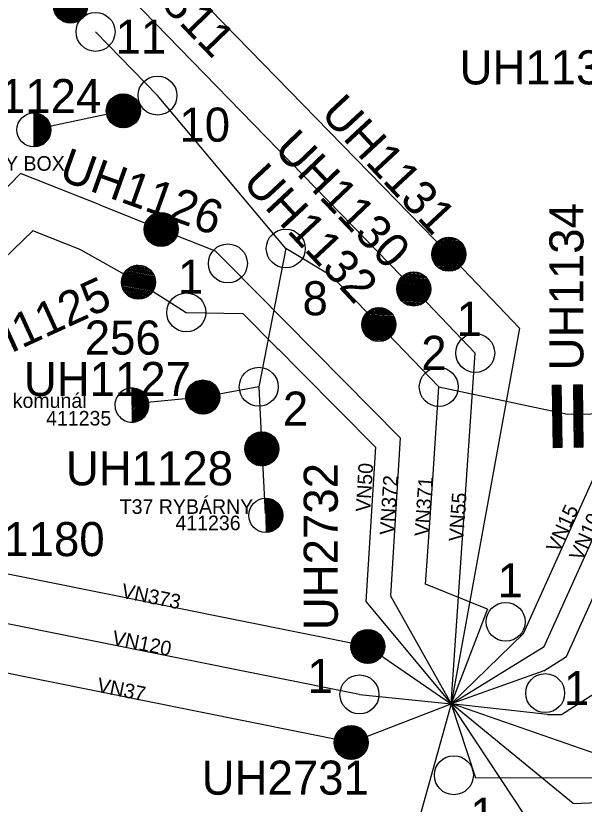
# Model space of a CAD drawing. Extents: x -541380 to -536551, y -1184364 to -1179471.
# Drawn here: x -537971 to -537387, y -1180734 to -1179924 of the extents above; entities that cross this region are included whole.
import ezdxf

# ---------------------------------------------------------------- set-up
doc = ezdxf.new("R2010")
doc.units = 0
for name, color, linetype in [('Default', 7, 'Continuous'), ('Vrstva 1', 7, 'Continuous'), ('Vrstva 2', 7, 'Continuous'), ('Vrstva 3', 7, 'Continuous'), ('Vrstva 5', 7, 'Continuous')]:
    doc.layers.add(name, color=color, linetype=linetype)

# ---------------------------------------------------------------- blocks, each defined once
blk = doc.blocks.new('PS100')
at = {"layer": 'Default'}
for p, q in [((-17.47, -0.71), (0.71, 17.47)), ((-17.47, 0.7), (-0.7, 17.47)), ((-17.37, -2.02), (2.02, 17.37)), ((-17.34, 2.25), (-2.25, 17.34)), ((-17.18, -3.25), (3.25, 17.18)), ((-17.03, 3.97), (-3.97, 17.03)), ((-16.92, -4.41), (4.41, 16.92)), ((-16.6, -5.5), (5.5, 16.6)), ((-16.43, 5.99), (-5.99, 16.43)), ((-16.22, -6.53), (6.53, 16.22)), ((-15.79, -7.52), (7.52, 15.79)), ((-15.31, -8.45), (8.45, 15.31)), ((-15.22, 8.61), (-8.61, 15.22)), ((-14.78, -9.34), (9.34, 14.78)), ((-14.22, -10.18), (10.18, 14.22)), ((-13.6, -10.99), (10.99, 13.6)), ((-12.95, -11.75), (11.75, 12.95)), ((-12.26, -12.47), (12.47, 12.26)), ((-11.53, -13.15), (13.15, 11.53)), ((-10.75, -13.79), (13.79, 10.75)), ((-9.94, -14.39), (14.39, 9.94)), ((-9.08, -14.95), (14.95, 9.08)), ((-8.18, -15.46), (15.46, 8.18)), ((-7.23, -15.92), (15.92, 7.23)), ((-6.23, -16.34), (16.34, 6.23)), ((-5.18, -16.7), (16.7, 5.18)), ((-4.07, -17.01), (17.01, 4.07)), ((-2.89, -17.25), (17.25, 2.89)), ((-1.64, -17.41), (17.41, 1.64)), ((-0.3, -17.48), (17.48, 0.3)), ((1.15, -17.45), (17.45, -1.15)), ((2.74, -17.27), (17.27, -2.74)), ((4.54, -16.89), (16.89, -4.54)), ((6.68, -16.16), (16.16, -6.68)), ((9.71, -14.54), (14.54, -9.71))]:
    blk.add_line(p, q, dxfattribs=at)
blk.add_circle((0, 0), 17.49, dxfattribs=at)
blk = doc.blocks.new('PS140')
at = {"layer": 'Default'}
for p, q in [((-17.49, -0.01), (0.01, 17.49)), ((-17.43, -1.37), (1.37, 17.43)), ((-17.42, 1.47), (-1.47, 17.42)), ((-17.29, -2.63), (2.63, 17.29)), ((-17.21, 3.1), (-3.1, 17.21)), ((-17.06, -3.82), (3.82, 17.06)), ((-16.77, -4.95), (4.95, 16.77)), ((-16.77, 4.95), (-4.95, 16.77)), ((-16.42, -6.01), (6.01, 16.42)), ((-16.02, -7.02), (7.02, 16.02)), ((-15.93, 7.2), (-7.2, 15.93)), ((-15.56, -7.98), (7.98, 15.56)), ((-15.06, -8.89), (8.89, 15.06)), ((-14.51, -9.76), (9.76, 14.51)), ((-13.92, -10.58), (10.58, 13.92)), ((-13.75, 10.8), (-10.8, 13.75)), ((-13.29, -11.36), (11.36, 13.29)), ((-12.62, -12.11), (12.11, 12.62)), ((-11.91, -12.81), (12.81, 11.91)), ((-11.15, -13.47), (13.47, 11.15)), ((-10.36, -14.09), (14.09, 10.36)), ((-9.52, -14.67), (14.67, 9.52)), ((-8.64, -15.2), (15.2, 8.64)), ((-7.72, -15.69), (15.69, 7.72)), ((-6.74, -16.13), (16.13, 6.74)), ((-5.72, -16.52), (16.52, 5.72)), ((-4.64, -16.86), (16.86, 4.64)), ((-3.5, -17.13), (17.13, 3.5)), ((-2.29, -17.34), (17.34, 2.29)), ((-1, -17.46), (17.46, 1)), ((0.39, -17.48), (17.48, -0.39)), ((1.91, -17.38), (17.38, -1.91)), ((3.59, -17.11), (17.11, -3.59)), ((5.53, -16.59), (16.59, -5.53)), ((7.96, -15.57), (15.57, -7.96))]:
    blk.add_line(p, q, dxfattribs=at)
blk.add_circle((0, 0), 17.49, dxfattribs=at)
blk = doc.blocks.new('PS150')
at = {"layer": 'Default'}
for p, q in [((-15.07, 22.36), (-7.37, 30.07)), ((-15.07, 23.78), (-8.78, 30.07)), ((-15.07, 25.19), (-10.2, 30.07)), ((-15.07, 26.6), (-11.61, 30.07)), ((-15.07, 28.02), (-13.03, 30.07)), ((-15.07, 29.43), (-14.44, 30.07)), ((-15.07, 20.95), (-6.51, 29.51)), ((-15.07, 19.53), (-6.51, 28.1)), ((-15.07, 18.12), (-6.51, 26.69)), ((-15.07, 16.71), (-6.51, 25.27)), ((6.66, 22.61), (14.12, 30.07)), ((6.66, 24.02), (12.7, 30.06)), ((6.66, 25.43), (11.29, 30.06)), ((6.66, 26.85), (9.87, 30.06)), ((6.66, 28.26), (8.46, 30.06)), ((6.66, 29.68), (7.04, 30.06)), ((6.66, 21.19), (15.22, 29.76)), ((6.66, 19.78), (15.22, 28.34)), ((6.66, 18.36), (15.22, 26.93)), ((6.66, 16.95), (15.22, 25.51)), ((-15.07, 15.29), (-6.51, 23.86)), ((-15.07, 13.88), (-6.51, 22.44)), ((-15.07, 12.46), (-6.51, 21.03)), ((-15.07, 11.05), (-6.51, 19.61)), ((-15.07, 9.64), (-6.51, 18.2)), ((-15.07, 8.22), (-6.51, 16.79)), ((6.66, 15.54), (15.22, 24.1)), ((6.66, 14.12), (15.22, 22.69)), ((6.66, 12.71), (15.22, 21.27)), ((6.66, 11.29), (15.22, 19.86)), ((6.66, 9.88), (15.22, 18.44)), ((6.66, 8.46), (15.22, 17.03)), ((-15.07, 6.81), (-6.51, 15.37)), ((-15.07, 5.39), (-6.51, 13.96)), ((-15.07, 3.98), (-6.5, 12.54)), ((-15.07, 2.56), (-6.5, 11.13)), ((-15.07, 1.15), (-6.5, 9.72)), ((-15.07, -0.26), (-6.5, 8.3)), ((6.66, 7.05), (15.22, 15.62)), ((6.66, 5.64), (15.22, 14.2)), ((6.66, 4.22), (15.22, 12.79)), ((6.66, 2.81), (15.22, 11.37)), ((6.66, 1.39), (15.22, 9.96)), ((6.66, -0.02), (15.22, 8.55)), ((-15.07, -1.68), (-6.5, 6.89)), ((-15.07, -3.09), (-6.5, 5.47)), ((-15.07, -4.51), (-6.5, 4.06)), ((-15.07, -5.92), (-6.5, 2.65)), ((-15.07, -7.33), (-6.5, 1.23)), ((6.66, -1.43), (15.22, 7.13)), ((6.66, -2.85), (15.22, 5.72)), ((6.66, -4.26), (15.22, 4.3)), ((6.66, -5.68), (15.22, 2.89)), ((6.66, -7.09), (15.22, 1.47)), ((6.66, -8.5), (15.22, 0.06)), ((-15.07, -8.75), (-6.5, -0.18)), ((-15.07, -10.16), (-6.5, -1.6)), ((-15.07, -11.58), (-6.5, -3.01)), ((-15.07, -12.99), (-6.5, -4.43)), ((-15.07, -14.4), (-6.5, -5.84)), ((-15.07, -15.82), (-6.5, -7.25)), ((6.66, -9.92), (15.22, -1.35)), ((6.66, -11.33), (15.22, -2.77)), ((6.66, -12.75), (15.22, -4.18)), ((6.66, -14.16), (15.23, -5.6)), ((6.66, -15.58), (15.23, -7.01)), ((-15.07, -17.23), (-6.5, -8.67)), ((-15.07, -18.65), (-6.5, -10.08)), ((-15.07, -20.06), (-6.5, -11.5)), ((-15.07, -21.48), (-6.5, -12.91)), ((-15.07, -22.89), (-6.5, -14.32)), ((-15.07, -24.3), (-6.5, -15.74)), ((6.66, -16.99), (15.23, -8.42)), ((6.66, -18.4), (15.23, -9.84)), ((6.66, -19.82), (15.23, -11.25)), ((6.66, -21.23), (15.23, -12.67)), ((6.66, -22.65), (15.23, -14.08)), ((6.66, -24.06), (15.23, -15.49)), ((-15.07, -25.72), (-6.5, -17.15)), ((-15.07, -27.13), (-6.5, -18.57)), ((-15.07, -28.55), (-6.5, -19.98)), ((-15.07, -29.96), (-6.5, -21.39)), ((-15.07, -31.37), (-6.5, -22.81)), ((-15.07, -32.79), (-6.5, -24.22)), ((6.66, -25.47), (15.23, -16.91)), ((6.66, -26.89), (15.23, -18.32)), ((6.66, -28.3), (15.23, -19.74)), ((6.66, -29.72), (15.23, -21.15)), ((6.66, -31.13), (15.23, -22.57)), ((6.66, -32.54), (15.23, -23.98)), ((-15.02, -34.16), (-6.5, -25.64)), ((-13.61, -34.16), (-6.5, -27.05)), ((-12.2, -34.16), (-6.5, -28.47)), ((-10.78, -34.16), (-6.5, -29.88)), ((-9.37, -34.16), (-6.5, -31.29)), ((6.66, -33.96), (15.23, -25.39)), ((7.87, -34.16), (15.23, -26.81)), ((9.29, -34.16), (15.23, -28.22)), ((10.7, -34.16), (15.23, -29.64)), ((12.12, -34.16), (15.23, -31.05)), ((-7.95, -34.16), (-6.5, -32.71)), ((-6.54, -34.16), (-6.5, -34.12)), ((13.53, -34.16), (15.23, -32.46)), ((14.95, -34.16), (15.23, -33.88))]:
    blk.add_line(p, q, dxfattribs=at)
for points in [[(-6.51, 30.07), (-6.5, -34.16), (-15.07, -34.16), (-15.07, 30.07)], [(15.22, 30.07), (15.23, -34.16), (6.66, -34.16), (6.66, 30.06)]]:
    blk.add_lwpolyline(points, close=True, dxfattribs=at)
blk = doc.blocks.new('PS610')
at = {"layer": 'Default'}
for p, q in [((0, 16.16), (1.27, 17.43)), ((0, 14.75), (2.54, 17.29)), ((0, 13.33), (3.75, 17.09)), ((0, 11.92), (4.86, 16.79)), ((0, 10.51), (5.93, 16.44)), ((0, 9.09), (6.95, 16.05)), ((0, 7.68), (7.9, 15.58)), ((0, 6.26), (8.83, 15.1)), ((0, 4.85), (9.69, 14.54)), ((0, 3.44), (10.52, 13.96)), ((0, 2.02), (11.3, 13.33)), ((0, 0.61), (12.05, 12.66)), ((0, -0.81), (12.76, 11.95)), ((0, -2.22), (13.42, 11.2)), ((0, -3.64), (14.05, 10.41)), ((0, -5.05), (14.62, 9.57)), ((0, -6.46), (15.17, 8.71)), ((0, -7.88), (15.65, 7.77)), ((0, -9.29), (16.1, 6.81)), ((0, -10.71), (16.49, 5.79)), ((0, -12.12), (16.83, 4.71)), ((0, -13.53), (17.12, 3.59)), ((0, -14.95), (17.32, 2.37)), ((0, -16.36), (17.44, 1.08)), ((0.29, -17.49), (17.48, -0.29)), ((1.78, -17.41), (17.4, -1.79)), ((3.46, -17.15), (17.14, -3.46)), ((5.36, -16.66), (16.65, -5.37)), ((7.78, -15.65), (15.64, -7.79))]:
    blk.add_line(p, q, dxfattribs=at)
blk.add_lwpolyline([(0, 17.5), (0, -17.5)], dxfattribs=at)
blk.add_circle((0, 0), 17.5, dxfattribs=at)
blk = doc.blocks.new('PS800')
at = {"layer": 'Vrstva 2'}
blk.add_circle((0, -0.01), 20, dxfattribs=at)
blk = doc.blocks.new('PS611')
at = {"layer": 'Default'}
for p, q in [((0, 16.16), (1.27, 17.43)), ((0, 14.75), (2.54, 17.29)), ((0, 13.33), (3.75, 17.09)), ((0, 11.92), (4.86, 16.79)), ((0, 10.51), (5.93, 16.44)), ((0, 9.09), (6.95, 16.05)), ((0, 7.68), (7.9, 15.58)), ((0, 6.26), (8.83, 15.1)), ((0, 4.85), (9.69, 14.54)), ((0, 3.44), (10.52, 13.96)), ((0, 2.02), (11.3, 13.33)), ((0, 0.61), (12.05, 12.66)), ((0, -0.81), (12.76, 11.95)), ((0, -2.22), (13.42, 11.2)), ((0, -3.64), (14.05, 10.41)), ((0, -5.05), (14.62, 9.57)), ((0, -6.46), (15.17, 8.71)), ((0, -7.88), (15.65, 7.77)), ((0, -9.29), (16.1, 6.81)), ((0, -10.71), (16.49, 5.79)), ((0, -12.12), (16.83, 4.71)), ((0, -13.53), (17.12, 3.59)), ((0, -14.95), (17.32, 2.37)), ((0, -16.36), (17.44, 1.08)), ((0.29, -17.49), (17.48, -0.29)), ((1.78, -17.41), (17.4, -1.79)), ((3.46, -17.15), (17.14, -3.46)), ((5.36, -16.66), (16.65, -5.37)), ((7.78, -15.65), (15.64, -7.79))]:
    blk.add_line(p, q, dxfattribs=at)
for points in [[(17.5, 0), (17.4, 1.83), (17.12, 3.64), (16.64, 5.4), (15.98, 7.11), (15.15, 8.75), (14.15, 10.28), (13, 11.71), (11.71, 13), (10.28, 14.15), (8.75, 15.15), (7.11, 15.98), (5.4, 16.64), (3.64, 17.12), (1.83, 17.4), (0, 17.5), (-1.83, 17.4), (-3.64, 17.12), (-5.41, 16.64), (-7.12, 15.98), (-8.75, 15.15), (-10.29, 14.15), (-11.71, 13), (-13.01, 11.71), (-14.16, 10.28), (-15.16, 8.75), (-15.99, 7.11), (-16.65, 5.4), (-17.12, 3.64), (-17.41, 1.83), (-17.5, 0), (-17.41, -1.83), (-17.12, -3.64), (-16.65, -5.41), (-15.99, -7.12), (-15.16, -8.75), (-14.16, -10.29), (-13.01, -11.71), (-11.71, -13.01), (-10.29, -14.16), (-8.75, -15.16), (-7.12, -15.99), (-5.41, -16.65), (-3.64, -17.12), (-1.83, -17.41), (0, -17.5), (1.83, -17.41), (3.64, -17.12), (5.4, -16.65), (7.12, -15.99), (8.75, -15.16), (10.28, -14.16), (11.71, -13.01), (13, -11.71), (14.15, -10.29), (15.15, -8.75), (15.98, -7.12), (16.64, -5.41), (17.12, -3.64), (17.4, -1.83), (17.5, 0)], [(0, 17.5), (0, -17.5)]]:
    blk.add_lwpolyline(points, dxfattribs=at)

msp = doc.modelspace()

# ---------------------------------------------------------------- linework, layer by layer
at = {"layer": 'Vrstva 1'}
for points in [[(-537562.4, -1180204.39), (-538043.71, -1179709.95), (-538197.36, -1179520.6)], [(-537976.73, -1179707.01), (-537526.24, -1180168.73)], [(-537825.63, -1180005.77), (-537889.29, -1179940.35)], [(-537693.84, -1180162.8), (-537825.63, -1180005.77)], [(-537860.74, -1180021.44), (-537952.62, -1180041)], [(-537885.05, -1180118.14), (-537966.34, -1180085.86), (-538066.86, -1180188.79)], [(-537523.8, -1180630.47), (-537428.24, -1180571.41), (-537346.89, -1180391.28), (-537127.07, -1180391.28), (-537127.07, -1180095.77), (-537320.92, -1180095.77)], [(-537885.05, -1180118.14), (-537821.94, -1180143.2)], [(-537449.57, -1180558.24), (-537363.04, -1180366.28), (-537152.07, -1180366.28), (-537152.07, -1180156.72), (-537176.86, -1180136.28)], [(-537904.35, -1180164.27), (-537953.84, -1180144.62), (-538175.11, -1180357.87), (-538433.96, -1180474.6)], [(-537821.94, -1180143.2), (-537766.49, -1180165.22), (-537753.34, -1180178.18)], [(-537904.35, -1180164.27), (-537845.26, -1180197.45)], [(-537693.84, -1180162.8), (-537721.6, -1180304.82)], [(-537646.5, -1180191.25), (-537693.84, -1180162.8)], [(-537526.24, -1180168.73), (-537453.84, -1180244.47)], [(-537753.34, -1180178.18), (-537576.18, -1180357.24), (-537586.28, -1180519.63), (-537523.8, -1180630.47)], [(-537598.13, -1180240.91), (-537646.5, -1180191.25)], [(-537845.26, -1180197.45), (-537796.09, -1180228.47)], [(-537562.4, -1180204.39), (-537499.22, -1180270.17)], [(-537796.09, -1180228.47), (-537737.83, -1180229.41), (-537702.61, -1180265)], [(-537536.66, -1180304.99), (-537598.13, -1180240.91)], [(-537453.84, -1180244.47), (-537523.8, -1180630.47)], [(-537702.61, -1180265), (-537701.07, -1180266.56)], [(-537701.07, -1180266.56), (-537680.03, -1180287.82)], [(-537523.8, -1180630.47), (-537499.22, -1180270.17)], [(-537680.03, -1180287.82), (-537677.7, -1180290.18)], [(-537677.7, -1180290.18), (-537601.83, -1180366.86), (-537611.69, -1180525.46), (-537523.8, -1180630.47)], [(-537721.6, -1180304.82), (-537779.05, -1180315.34)], [(-537721.6, -1180304.82), (-537718.46, -1180368.51)], [(-537542.57, -1180394.7), (-537536.67, -1180304.99)], [(-537536.67, -1180304.99), (-537404.27, -1180333.02)], [(-537779.05, -1180315.34), (-537850.49, -1180322.28)], [(-537404.27, -1180333.02), (-537332.78, -1180332.02)], [(-537718.46, -1180368.51), (-537714.91, -1180434.92)], [(-537548.72, -1180483.75), (-537542.57, -1180394.7)], [(-537428.88, -1180596.69), (-537405.46, -1180581.7), (-537330.75, -1180416.28), (-537012.78, -1180416.28), (-537012.78, -1180493.35)], [(-537609.61, -1180571.48), (-538081.74, -1180476.65)], [(-537550.35, -1180507.47), (-537548.72, -1180483.75)], [(-537486.45, -1180533.1), (-537550.35, -1180507.47)], [(-537618.16, -1180620.76), (-538090.97, -1180525.86)], [(-537486.45, -1180533.1), (-537523.8, -1180630.47)], [(-537449.57, -1180558.24), (-537523.8, -1180630.47)], [(-537609.61, -1180571.48), (-537523.8, -1180630.47)], [(-537626.66, -1180670.05), (-538100.03, -1180575.04)], [(-537424.91, -1180641.51), (-537410.41, -1180641.53), (-537356.43, -1180606.96), (-537203.9, -1180606.98), (-537174.9, -1180575.48)], [(-537428.88, -1180596.69), (-537523.8, -1180630.47)], [(-537618.16, -1180620.76), (-537523.8, -1180630.47)], [(-537626.66, -1180670.05), (-537523.8, -1180630.47)], [(-537523.8, -1180630.47), (-537559.12, -1180757.17)], [(-537424.91, -1180641.51), (-537523.8, -1180630.47)], [(-537422.64, -1180783.71), (-537523.8, -1180630.47)], [(-537523.8, -1180630.47), (-537498.93, -1180706.24)], [(-537398.43, -1180732.83), (-537523.78, -1180630.2)], [(-537374.22, -1180681.96), (-537523.78, -1180630.2)], [(-537498.93, -1180706.24), (-537274.96, -1180706.21), (-537274.96, -1180642.57)], [(-537398.43, -1180732.83), (-537214.9, -1180725.32), (-537042.1, -1180687.63)]]:
    msp.add_lwpolyline(points, dxfattribs=at)

# ---------------------------------------------------------------- block references
at = {"layer": 'Vrstva 2'}
for name, p, rotation in [('PS100', (-537915.01, -1179913.92), -131.35687151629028), ('PS140', (-537860.74, -1180021.44), -178.35003060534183), ('PS140', (-537821.94, -1180143.2), 41.21475276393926), ('PS140', (-537526.25, -1180168.73), -49.236283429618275), ('PS140', (-537845.26, -1180197.44), 124.16993897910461), ('PS140', (-537562.4, -1180204.39), -49.669405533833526), ('PS140', (-537598.13, -1180240.91), -48.565561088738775), ('PS140', (-537779.05, -1180315.34), 22.913119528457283), ('PS150', (-537404.27, -1180333.02), 0.7996121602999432), ('PS140', (-537718.46, -1180368.51), -80.21485832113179), ('PS100', (-537609.61, -1180571.48), 29.01520613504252), ('PS100', (-537626.66, -1180670.05), -108.56155173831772)]:
    msp.add_blockref(name, p, dxfattribs=dict(at, rotation=rotation))
at = {"layer": 'Vrstva 3'}
for name, p, rotation in [('PS610', (-537952.62, -1180041), 0.018238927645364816), ('PS611', (-537851.91, -1180323.61), 0.5335249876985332), ('PS610', (-537714.44, -1180436.84), 0.9896083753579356)]:
    msp.add_blockref(name, p, dxfattribs=dict(at, rotation=rotation))
at = {"layer": 'Vrstva 5'}
msp.add_blockref('PS800', (-537889.29, -1179940.35), dxfattribs=at)
for p, rotation in [((-537825.63, -1180005.77), -48.89123898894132), ((-537693.84, -1180162.8), -49.63510274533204), ((-537753.34, -1180178.18), -30.129919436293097), ((-537796.09, -1180228.47), -34.42942502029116), ((-537499.22, -1180270.17), 130.68397226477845), ((-537536.67, -1180304.99), 131.57130551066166), ((-537721.6, -1180304.82), -83.86399442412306), ((-537467.9, -1180546.18), 54.3026055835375), ((-537427.32, -1180619.41), 67.58060838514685), ((-537618.16, -1180620.76), 78.12650001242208), ((-537521.14, -1180703.7), 54.32645558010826)]:
    msp.add_blockref('PS800', p, dxfattribs=dict(at, rotation=rotation))

# ---------------------------------------------------------------- texts
at = {"layer": 'Vrstva 1'}
for s, rotation, p in [('VN50', 86.443, (-537607.09, -1180433.63)), ('VN372', 86.443, (-537582.36, -1180457.47)), ('VN371', 86.053, (-537546.68, -1180458.87)), ('VN55', 86.053, (-537511.45, -1180464.09)), ('VN15', 65.736, (-537413.26, -1180476.09)), ('VN10', 65.694, (-537389.72, -1180484.75)), ('VN373', 348.643, (-537863.67, -1180521.3)), ('VN120', 348.651, (-537873.23, -1180569.46)), ('VN37', 348.651, (-537888.74, -1180618.01))]:
    msp.add_text(s, height=15, rotation=rotation, dxfattribs=at).set_placement(p)
at = {"layer": 'Vrstva 2'}
for s, rotation, p in [('UH2811', 314.088, (-537887.82, -1179845.7)), ('UH1131', 312.966, (-537659.22, -1180025.26)), ('UH1130', 313.698, (-537707.19, -1180061.84)), ('UH1126', 340.259, (-537928.49, -1180091.77)), ('UH1132', 313.059, (-537739.62, -1180096.04)), ('UH1134', 89.967, (-537388.08, -1180287.97)), ('UH1125', 24.548, (-538026.58, -1180293.66)), ('UH2732', 90, (-537640.43, -1180554.81))]:
    msp.add_text(s, height=35, rotation=rotation, dxfattribs=at).set_placement(p)
for s, p in [('UH1138', (-537515.27, -1179994.31)), ('UH1124', (-538055.12, -1180023.83)), ('UH1127', (-537962.94, -1180314.35)), ('UH1128', (-537919.77, -1180406.06)), ('UH1180', (-538051.67, -1180478.74)), ('UH2731', (-537780.23, -1180723.72))]:
    msp.add_text(s, height=35, dxfattribs=at).set_placement(p)
at = {"layer": 'Vrstva 3'}
for s, p in [('T71 MY BOX', (-538039.14, -1180082.96)), ('T21 komunál', (-538014.51, -1180326.51)), ('411235', (-537940.11, -1180344.62)), ('T37 RYBÁRNY', (-537864.46, -1180435.35)), ('411236', (-537807.2, -1180452.12))]:
    msp.add_text(s, height=15, dxfattribs=at).set_placement(p)
at = {"layer": 'Vrstva 5'}
for s, p in [('11', (-537868.8, -1179962.89)), ('10', (-537803.16, -1180053.12)), ('1', (-537804.6, -1180209.33)), ('8', (-537676.64, -1180231.42)), ('1', (-537518.39, -1180252.55)), ('256', (-537900.4, -1180271.81)), ('2', (-537554.64, -1180287.49)), ('2', (-537696.87, -1180344.77)), ('1', (-537476.26, -1180521.16)), ('1', (-537671.62, -1180619.21)), ('1', (-537408.09, -1180631.72)), ('1', (-537504.3, -1180761.69))]:
    msp.add_text(s, height=35, dxfattribs=at).set_placement(p)

doc.saveas('drawing.dxf')
